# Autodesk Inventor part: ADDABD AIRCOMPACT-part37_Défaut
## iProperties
Shininess: 64.0
Length Units: 11269
Angle Units: 11279
Time Units: 11290
Mass Units: 11283
Length Display Precision: 3
Angle Display Precision: 2
Compacted: True
Part Number: ADDABD AIRCOMPACT-part37_Défaut
Document SubType Name: Modeling
Created: 2006-01
Material: Par défaut
Designer: riri
Density: 0.0
Volumn: 0.0
Area: 0.0
PropertySet Name: Model Information
Control State: 0
Master: False
Checked Out: False
Author: riri
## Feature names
1. Base1
